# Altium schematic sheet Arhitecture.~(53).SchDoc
size A3; SheetNumber: 1; SheetTotal: 11
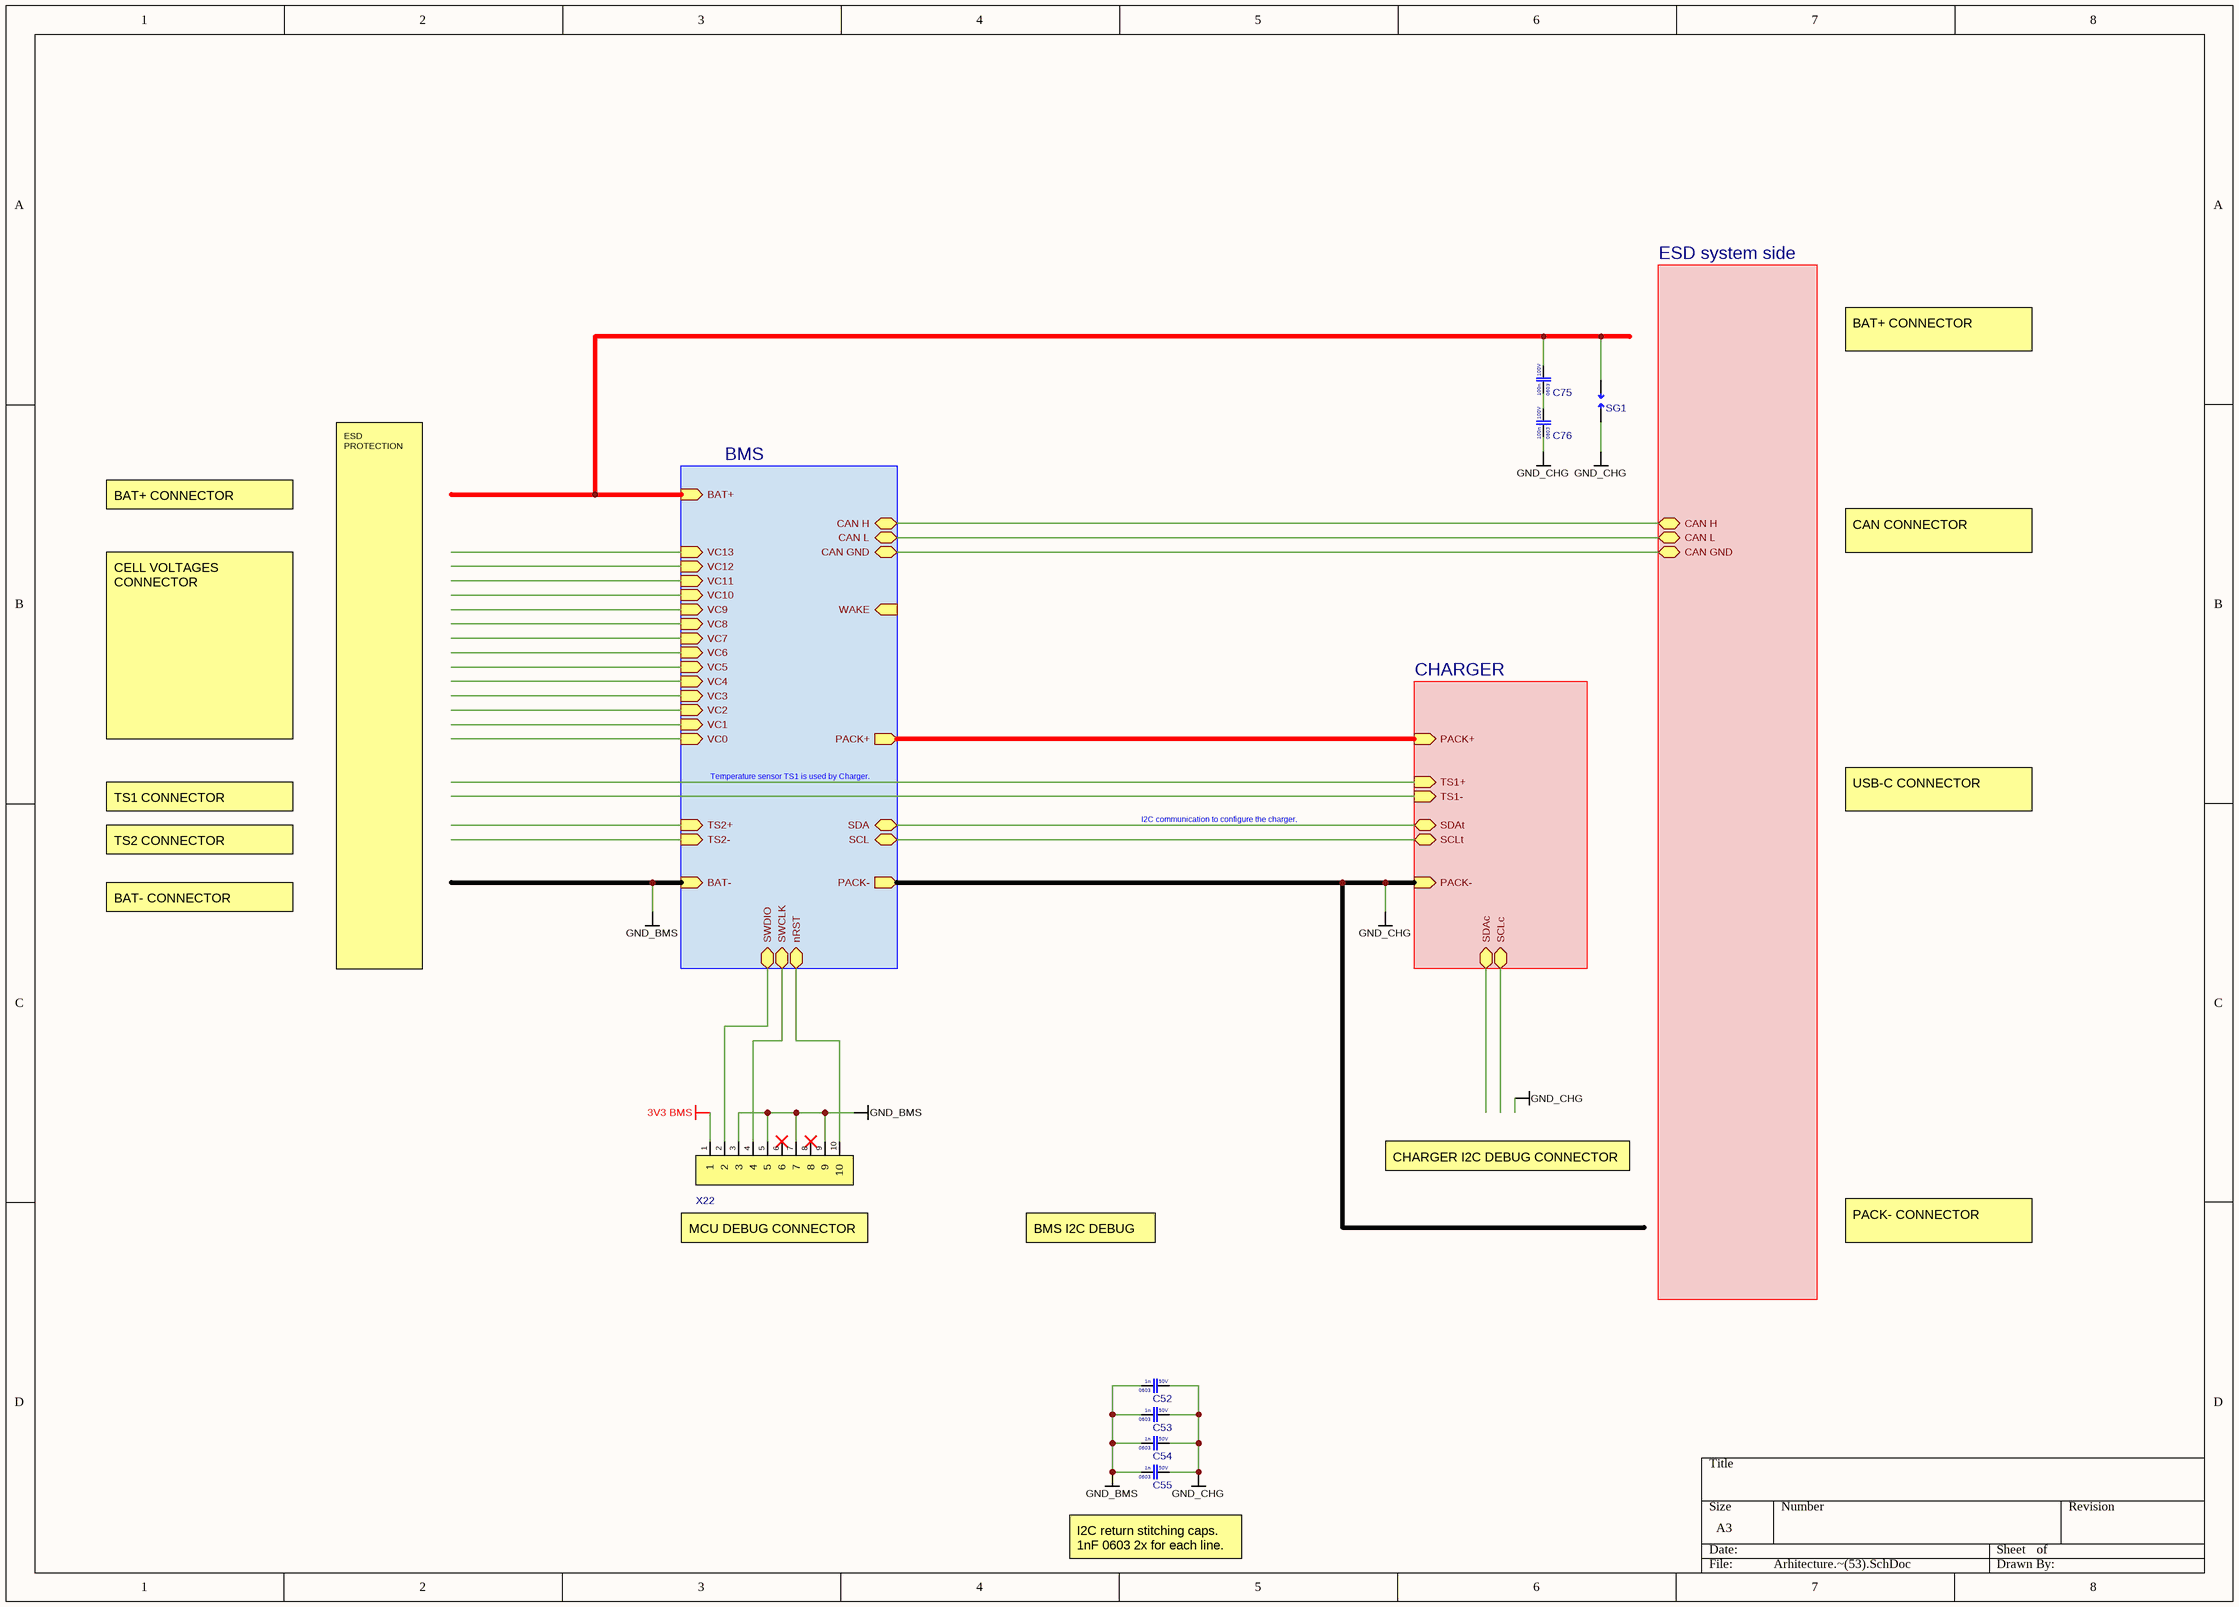
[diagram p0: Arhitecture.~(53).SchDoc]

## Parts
C52  Voltage Rating: 50V  Case Code (Imperial): 0603  Capacitance: 1n  [CAP 0603]  (hidden comment: CL10B102KB8NNNC)
C53  Voltage Rating: 50V  Case Code (Imperial): 0603  Capacitance: 1n  [CAP 0603]  (hidden comment: CL10B102KB8NNNC)
C54  Voltage Rating: 50V  Case Code (Imperial): 0603  Capacitance: 1n  [CAP 0603]  (hidden comment: CL10B102KB8NNNC)
C55  Voltage Rating: 50V  Case Code (Imperial): 0603  Capacitance: 1n  [CAP 0603]  (hidden comment: CL10B102KB8NNNC)
C75  Voltage Rating: 100V  Case Code (Imperial): 0603  Capacitance: 100n  [CAP 0603]  (hidden comment: CC0603KRX7R0BB104)
C76  Voltage Rating: 100V  Case Code (Imperial): 0603  Capacitance: 100n  [CAP 0603]  (hidden comment: CC0603KRX7R0BB104)
SG1  Spark gap  [Spark Gap 0.270mm]  (value not drawn)  (no BOM)
X22  HX IDC127-2-05-S-4.9  [JTAG Cortex connector]  (value not drawn)

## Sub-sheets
BMS = BMS.SchDoc: BAT+ (in), BAT- (in), VC0 (in), VC1 (in), VC2 (in), VC3 (in), VC4 (in), VC5 (in), VC6 (in), VC7 (in), VC8 (in), VC9 (in), VC10 (in), VC11 (in), VC12 (in), VC13 (in), PACK+ (out), PACK- (out), SCL (bidir), SDA (bidir), CAN H (bidir), CAN L (bidir), TS2+ (in), TS2- (in), WAKE (in), SWDIO (bidir), SWCLK (bidir), nRST (bidir), CAN GND (bidir)
CHARGER = CHARGER.SchDoc: PACK+ (in), PACK- (in), SDAt (bidir), SCLt (bidir), TS1+ (in), TS1- (in), SDAc (bidir), SCLc (bidir)
ESD system side = ESD system side.SchDoc: CAN H (bidir), CAN L (bidir), CAN GND (bidir)

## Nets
3V3 BMS: X22.1
GND_BMS: C52.1 C53.1 C54.1 C55.1 X22.3 X22.5 X22.7 X22.9 ; sheet BMS/BAT-
GND_CHG: C52.2 C53.2 C54.2 C55.2 C76.1 SG1.1 ; sheet BMS/PACK-, sheet CHARGER/PACK-
NetC75_1: C75.1 C76.2
NetC75_2: C75.2 SG1.2 ; sheet BMS/BAT+
NetX22_2: X22.2 ; sheet BMS/SWDIO
NetX22_4: X22.4 ; sheet BMS/SWCLK
NetX22_10: X22.10 ; sheet BMS/nRST
(unnamed): sheet BMS/PACK+, sheet CHARGER/PACK+
(unnamed): sheet BMS/SCL, sheet CHARGER/SCLt  [a separate net that carries the same name]
(unnamed): sheet BMS/SDA, sheet CHARGER/SDAt  [a separate net that carries the same name]
(unnamed): sheet BMS/CAN H, sheet ESD system side/CAN H  [a separate net that carries the same name]
(unnamed): sheet BMS/CAN L, sheet ESD system side/CAN L  [a separate net that carries the same name]
(unnamed): sheet BMS/CAN GND, sheet ESD system side/CAN GND  [a separate net that carries the same name]

Not connected (* = marked no-connect by the designer): X22 6* 8*

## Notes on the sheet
- BAT+ CONNECTOR
- CAN CONNECTOR
- CELL VOLTAGES CONNECTOR
- TS1 CONNECTOR
- Temperature sensor TS1 is used by Charger.
- I2C communication to configure the charger.
- USB-C CONNECTOR
- BAT- CONNECTOR
- TS2 CONNECTOR
- ESD PROTECTION
- CHARGER I2C DEBUG CONNECTOR
- MCU DEBUG CONNECTOR
- BMS I2C DEBUG CONNECTOR
- PACK- CONNECTOR
- (near C55) I2C return stitching caps.
  1nF 0603 2x for each line.

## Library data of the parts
C52-C55 = CL10B102KB8NNNC: Cap 1nF 50V 0603 X7R; Manufacturer: Samsung
C75 C76 = CC0603KRX7R0BB104: Cap 100nF 100V 0603 X7R; Manufacturer: YAGEO
SG1 = Spark gap: Generic Spark gap symbol
X22 = HX IDC127-2-05-S-4.9: JTAG Cortex MCU Debug connector 2x5P 1.27mmP; Manufacturer: hanxia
